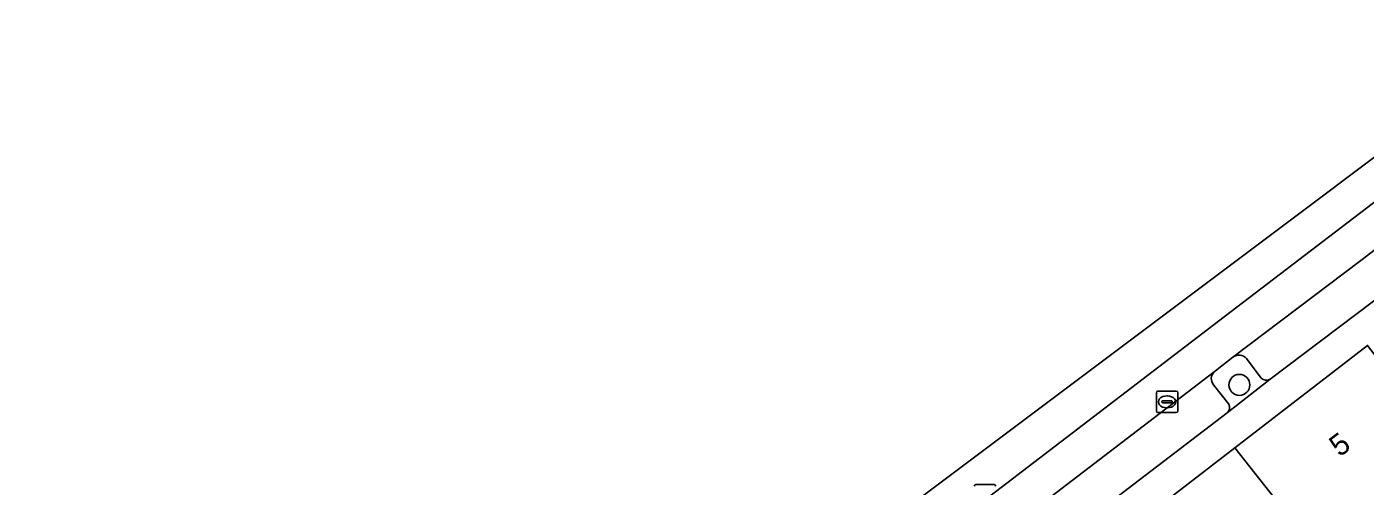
# Model space of a CAD drawing. Extents: x 159499 to 160349, y 382524 to 383273.
# Drawn here: x 159878.6 to 159941.1, y 383243.2 to 383264.6 of the extents above; entities that cross this region are included whole.
import ezdxf

# ---------------------------------------------------------------- set-up
doc = ezdxf.new("R2010")
doc.units = 0
for name, color, linetype in [('IMGEO_Boom', 7, 'Continuous'), ('IMGEO_Groenvoorziening', 7, 'Continuous'), ('IMGEO_Kolk', 7, 'Continuous'), ('IMGEO_Pand', 7, 'Continuous'), ('IMGEO_Pand_nummerreeks', 7, 'Continuous'), ('IMGEO_Parkeervlak_open', 7, 'Continuous'), ('IMGEO_Rijbaan_lokaal_gesloten', 7, 'Continuous'), ('IMGEO_Rijbaan_lokaal_open', 7, 'Continuous'), ('IMGEO_Rioolput', 7, 'Continuous'), ('IMGEO_Voetpad_open', 7, 'Continuous')]:
    doc.layers.add(name, color=color, linetype=linetype)

msp = doc.modelspace()

# ---------------------------------------------------------------- linework, layer by layer
at = {"layer": 'IMGEO_Boom'}
msp.add_circle((159935.201, 383247.909), 0.489, dxfattribs=at)
at = {"layer": 'IMGEO_Groenvoorziening'}
for points in [[(159934.9, 383249.209), (159934.091, 383248.562), (159934.028, 383248.514)], [(159936.212, 383248.227), (159935.537, 383249.146)], [(159933.988, 383247.918), (159934.706, 383247.005)], [(159934.632, 383246.606), (159936.639, 383248.179)]]:
    msp.add_lwpolyline(points, dxfattribs=at)
for centre, radius, start, end in [((159935.183, 383248.821), 0.48, 42.57553, 126.12797), ((159934.324, 383248.195), 0.435, 132.82316, 219.49765), ((159936.454, 383248.452), 0.33, 222.99472, 304.17765), ((159934.437, 383246.849), 0.311, 308.81098, 30.17521)]:
    msp.add_arc(centre, radius, start, end, dxfattribs=at)
at = {"layer": 'IMGEO_Kolk'}
for p, q in [((159931.325, 383246.692), (159931.325, 383247.544)), ((159931.4, 383247.618), (159932.252, 383247.618)), ((159931.813, 383247.398), (159931.838, 383247.398)), ((159932.326, 383247.544), (159932.326, 383246.692)), ((159932.252, 383246.618), (159931.4, 383246.618)), ((159931.584, 383247.112), (159931.584, 383247.124)), ((159932.022, 383247.075), (159931.624, 383247.075)), ((159931.627, 383247.161), (159932.025, 383247.161)), ((159931.836, 383246.838), (159931.811, 383246.838)), ((159932.068, 383247.124), (159932.068, 383247.112))]:
    msp.add_line(p, q, dxfattribs=at)
for points in [[(159931.325, 383246.692), (159931.325, 383247.544)], [(159931.4, 383247.618), (159932.252, 383247.618)], [(159932.326, 383247.544), (159932.326, 383246.692)], [(159932.252, 383246.618), (159931.4, 383246.618)]]:
    msp.add_lwpolyline(points, dxfattribs=at)
for centre, radius, start, end in [((159931.402, 383247.542), 0.0765, 91.55205, 178.44795), ((159931.402, 383247.542), 0.0765, 91.55205, 178.44795), ((159932.25, 383247.542), 0.0765, 1.55205, 88.44795), ((159932.25, 383247.542), 0.0765, 1.55205, 88.44795), ((159931.402, 383246.694), 0.0765, 181.55205, 268.44795), ((159931.402, 383246.694), 0.0765, 181.55205, 268.44795), ((159931.624, 383247.121), 0.0403, 85.87752, 175.75265), ((159931.621, 383247.111), 0.0366, 178.93798, 274.71019), ((159932.025, 383247.118), 0.043, 264.86636, 352.45326), ((159932.029, 383247.123), 0.0386, 1.73085, 96.63898), ((159932.25, 383246.694), 0.0765, 271.55205, 358.44795), ((159932.25, 383246.694), 0.0765, 271.55205, 358.44795)]:
    msp.add_arc(centre, radius, start, end, dxfattribs=at)
for centre, major_axis, ratio, start_param, end_param in [((159931.812, 383247.118), (-0.387, 0.002), 0.722429, 4.712389, 7.853982), ((159931.837, 383247.118), (-0.39, 0.002), 0.717154, 1.570796, 4.712389)]:
    msp.add_ellipse(centre, major_axis=major_axis, ratio=ratio, start_param=start_param, end_param=end_param, dxfattribs=at)
at = {"layer": 'IMGEO_Pand'}
for points in [[(159943.034, 383247.333), (159941.192, 383249.757), (159934.989, 383244.971), (159940.069, 383238.544), (159946.121, 383243.176)], [(159940.069, 383238.544), (159934.989, 383244.971), (159931.169, 383242.023), (159929.264, 383240.554), (159934.482, 383233.819), (159934.801, 383233.463), (159936.629, 383231.423), (159939.389, 383233.536), (159937.224, 383236.366)]]:
    msp.add_lwpolyline(points, close=True, dxfattribs=at)
at = {"layer": 'IMGEO_Parkeervlak_open'}
for points in [[(159949.93, 383260.671), (159948.318, 383259.44), (159940.88, 383253.723), (159934.9, 383249.209)], [(159936.639, 383248.179), (159942.234, 383252.401), (159950.537, 383258.714)], [(159935.537, 383249.146), (159936.212, 383248.227)], [(159934.028, 383248.514), (159911.61, 383231.36), (159909.455, 383229.758)], [(159934.706, 383247.005), (159933.988, 383247.918)], [(159911.186, 383228.688), (159934.632, 383246.606)]]:
    msp.add_lwpolyline(points, dxfattribs=at)
for centre, radius, start, end in [((159935.183, 383248.821), 0.48, 42.57553, 126.12797), ((159934.324, 383248.195), 0.435, 132.82316, 219.49765), ((159936.454, 383248.452), 0.33, 222.99472, 304.17765), ((159934.437, 383246.849), 0.311, 308.81098, 30.17521)]:
    msp.add_arc(centre, radius, start, end, dxfattribs=at)
at = {"layer": 'IMGEO_Rijbaan_lokaal_gesloten'}
msp.add_lwpolyline([(159883.795, 383210.694), (159887.039, 383213.051), (159892.738, 383217.167), (159893.523, 383217.744), (159899.156, 383221.901), (159902.022, 383224.051), (159903.898, 383225.496), (159908.278, 383228.856), (159909.455, 383229.758), (159911.61, 383231.36), (159934.028, 383248.514), (159934.091, 383248.562), (159934.9, 383249.209), (159940.88, 383253.723), (159948.318, 383259.44), (159949.93, 383260.671), (159949.975, 383260.706), (159951.658, 383262.016), (159950.623, 383263.397), (159934.232, 383250.883), (159922.547, 383241.953), (159913.257, 383234.839), (159906.328, 383229.559)], dxfattribs=at)
at = {"layer": 'IMGEO_Rijbaan_lokaal_open'}
msp.add_lwpolyline([(159906.328, 383229.559), (159913.257, 383234.839), (159922.547, 383241.953), (159934.232, 383250.883), (159950.623, 383263.397), (159949.617, 383264.636), (159870.405, 383205.208), (159782.678, 383149.411)], dxfattribs=at)
at = {"layer": 'IMGEO_Rioolput'}
msp.add_line((159922.893, 383243.251), (159923.745, 383243.251), dxfattribs=at)
msp.add_lwpolyline([(159922.893, 383243.251), (159923.745, 383243.251)], dxfattribs=at)
for centre, start, end in [((159922.895, 383243.175), 91.55205, 178.44795), ((159922.895, 383243.175), 91.55205, 178.44795), ((159923.743, 383243.175), 1.55205, 88.44795), ((159923.743, 383243.175), 1.55205, 88.44795)]:
    msp.add_arc(centre, 0.0765, start, end, dxfattribs=at)
at = {"layer": 'IMGEO_Voetpad_open'}
for points in [[(159950.537, 383258.714), (159942.234, 383252.401), (159936.639, 383248.179), (159934.632, 383246.606), (159911.186, 383228.688), (159909.417, 383227.302), (159908.278, 383228.856), (159903.898, 383225.496)], [(159872.426, 383197.959), (159878.835, 383202.07), (159880.573, 383203.196), (159886.77, 383207.907), (159889.161, 383209.735), (159890.438, 383208.075), (159894.929, 383211.514), (159895.81, 383212.215), (159894.565, 383213.853), (159896.852, 383215.608), (159900.7, 383218.561), (159906.926, 383223.34), (159909.29, 383225.178), (159914.185, 383228.927), (159914.452, 383229.133), (159919.25, 383232.832), (159924.217, 383236.662), (159929.264, 383240.554), (159931.169, 383242.023), (159934.989, 383244.971), (159941.192, 383249.757)]]:
    msp.add_lwpolyline(points, dxfattribs=at)

# ---------------------------------------------------------------- texts
at = {"layer": 'IMGEO_Pand_nummerreeks'}
msp.add_text('5', height=1, rotation=37.44852, dxfattribs=at).set_placement((159939.889, 383244.514))

doc.saveas('drawing.dxf')
